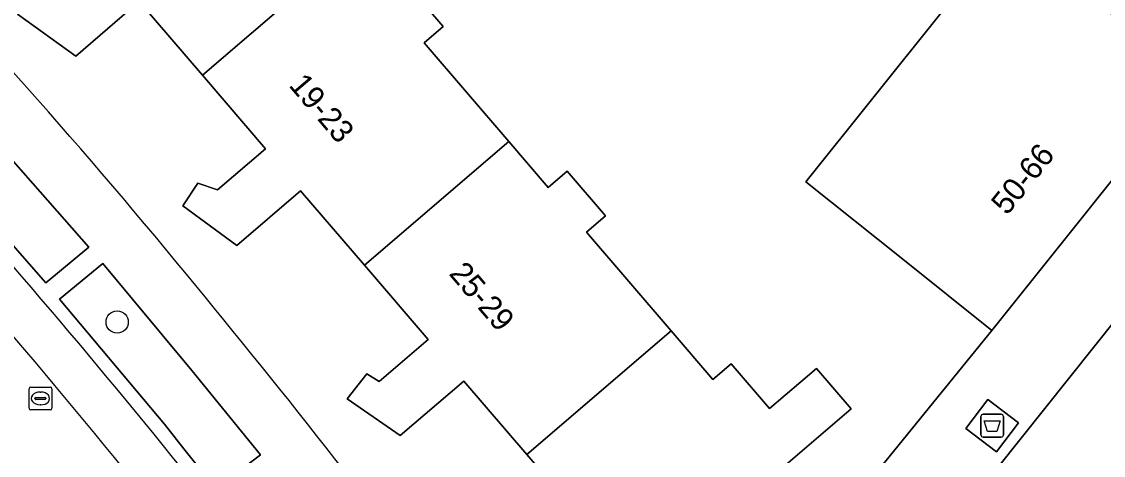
# Model space of a CAD drawing. Extents: x 159888 to 160761, y 384031 to 384750.
# Drawn here: x 160231.32 to 160278.81, y 384372.87 to 384391.93 of the extents above; entities that cross this region are included whole.
import ezdxf

# ---------------------------------------------------------------- set-up
doc = ezdxf.new("R2010")
doc.units = 0
for name, color, linetype in [('IMGEO_Afval_apart_plaats', 7, 'Continuous'), ('IMGEO_Berm_groen', 7, 'Continuous'), ('IMGEO_Boom', 7, 'Continuous'), ('IMGEO_Erf', 7, 'Continuous'), ('IMGEO_Fietspad_gesloten', 7, 'Continuous'), ('IMGEO_Groenvoorziening', 7, 'Continuous'), ('IMGEO_Pand', 7, 'Continuous'), ('IMGEO_Pand_nummerreeks', 7, 'Continuous'), ('IMGEO_Parkeervlak_open', 7, 'Continuous'), ('IMGEO_Rijbaan_lokaal_open', 7, 'Continuous'), ('IMGEO_Rioolput', 7, 'Continuous'), ('IMGEO_Voetpad_gesloten', 7, 'Continuous'), ('IMGEO_Voetpad_open', 7, 'Continuous')]:
    doc.layers.add(name, color=color, linetype=linetype)

msp = doc.modelspace()

# ---------------------------------------------------------------- linework, layer by layer
at = {"layer": 'IMGEO_Afval_apart_plaats'}
for p, q in [((160273.44, 384373.772), (160273.44, 384374.572)), ((160273.44, 384374.572), (160273.44, 384373.772)), ((160273.54, 384374.672), (160274.33, 384374.672)), ((160274.33, 384374.672), (160273.54, 384374.672)), ((160274.43, 384374.572), (160274.43, 384373.772)), ((160274.43, 384373.772), (160274.43, 384374.572)), ((160274.33, 384373.672), (160273.54, 384373.672)), ((160273.54, 384373.672), (160274.33, 384373.672))]:
    msp.add_line(p, q, dxfattribs=at)
msp.add_lwpolyline([(160273.583, 384374.386), (160274.287, 384374.386), (160274.138, 384373.916), (160273.732, 384373.916), (160273.583, 384374.386)], dxfattribs=at)
for centre, start, end in [((160273.54, 384374.572), 90, 180), ((160273.54, 384374.572), 90, 180), ((160274.33, 384374.572), 0, 90), ((160274.33, 384374.572), 360, 90), ((160273.54, 384373.772), 180, 270), ((160273.54, 384373.772), 180, 270), ((160274.33, 384373.772), 270, 0), ((160274.33, 384373.772), 270, 0)]:
    msp.add_arc(centre, 0.1, start, end, dxfattribs=at)
at = {"layer": 'IMGEO_Berm_groen'}
msp.add_arc((159956.836, 384149.758), 348.241, 34.54418, 40.04879, dxfattribs=at)
at = {"layer": 'IMGEO_Boom'}
msp.add_circle((160235.515, 384378.728), 0.489, dxfattribs=at)
at = {"layer": 'IMGEO_Erf'}
for points in [[(160242.027, 384386.34), (160239.258, 384389.573), (160236.489, 384392.807), (160233.695, 384390.414), (160231.142, 384392.248), (160231.874, 384393.353), (160232.674, 384392.788), (160234.835, 384394.639), (160232.048, 384397.893), (160229.261, 384401.148), (160226.47, 384398.758), (160223.915, 384400.407), (160224.746, 384401.572), (160225.516, 384401.057), (160227.729, 384402.952), (160224.921, 384406.231), (160222.112, 384409.511), (160219.269, 384407.076), (160216.817, 384408.667), (160215.325, 384405.834), (160223.225, 384397.993)], [(160248.153, 384393.671), (160249.832, 384391.711), (160248.995, 384390.994), (160252.709, 384386.658), (160254.444, 384384.632), (160255.28, 384385.348), (160256.959, 384383.388), (160256.122, 384382.671), (160259.836, 384378.335), (160261.666, 384376.198), (160262.477, 384376.892), (160264.162, 384374.923), (160266.223, 384376.687), (160267.744, 384374.911), (160264.872, 384372.453), (160267.058, 384369.901), (160273.92, 384378.359), (160270.015, 384381.482), (160265.753, 384384.892), (160274.58, 384395.925)], [(160251.391, 384364.439), (160254.889, 384359.573), (160259.602, 384363.534), (160260.735, 384364.486), (160257.748, 384367.974), (160254.967, 384365.592), (160252.638, 384367.22), (160253.369, 384368.345), (160254.116, 384367.849), (160256.256, 384369.681), (160253.495, 384372.905), (160250.734, 384376.129), (160247.942, 384373.738), (160245.621, 384375.35), (160246.472, 384376.455), (160247.014, 384376.12), (160249.168, 384377.959), (160246.369, 384381.228), (160243.569, 384384.497), (160240.766, 384382.096), (160238.402, 384383.829), (160239.065, 384384.832), (160239.915, 384384.532), (160242.027, 384386.34)]]:
    msp.add_lwpolyline(points, dxfattribs=at)
for centre, radius, start, end in [((160022.988, 384203.662), 279.033, 39.41659, 44.14248), ((159928.033, 384124.513), 402.647, 36.57478, 39.53815)]:
    msp.add_arc(centre, radius, start, end, dxfattribs=at)
at = {"layer": 'IMGEO_Fietspad_gesloten'}
msp.add_arc((159956.836, 384149.758), 348.241, 34.54418, 40.04879, dxfattribs=at)
at = {"layer": 'IMGEO_Groenvoorziening'}
for points in [[(160227.106, 384390.153), (160225.267, 384388.561), (160232.388, 384380.442), (160234.273, 384382.022)], [(160234.889, 384381.305), (160232.98, 384379.738), (160237.599, 384374.245), (160238.44, 384373.16), (160239.842, 384371.394), (160241.807, 384372.897), (160238.79, 384376.591)]]:
    msp.add_lwpolyline(points, close=True, dxfattribs=at)
at = {"layer": 'IMGEO_Pand'}
for points in [[(160245.577, 384394.985), (160241.863, 384399.321), (160242.7, 384400.038), (160241.021, 384401.998), (160240.185, 384401.282), (160238.416, 384403.347), (160232.048, 384397.893), (160234.835, 384394.639), (160232.674, 384392.788), (160231.874, 384393.353), (160231.142, 384392.248), (160233.695, 384390.414), (160236.489, 384392.807), (160239.258, 384389.573)], [(160274.58, 384395.925), (160265.753, 384384.892), (160270.015, 384381.482), (160273.92, 384378.359), (160282.747, 384389.392)], [(160248.995, 384390.994), (160249.832, 384391.711), (160248.153, 384393.671), (160247.317, 384392.955), (160245.577, 384394.985), (160239.258, 384389.573), (160242.027, 384386.34), (160239.915, 384384.532), (160239.065, 384384.832), (160238.402, 384383.829), (160240.766, 384382.096), (160243.569, 384384.497), (160246.369, 384381.228), (160252.709, 384386.658)], [(160256.122, 384382.671), (160256.959, 384383.388), (160255.28, 384385.348), (160254.444, 384384.632), (160252.709, 384386.658), (160246.369, 384381.228), (160249.168, 384377.959), (160247.014, 384376.12), (160246.472, 384376.455), (160245.621, 384375.35), (160247.942, 384373.738), (160250.734, 384376.129), (160253.495, 384372.905), (160259.836, 384378.335)], [(160264.872, 384372.453), (160267.744, 384374.911), (160266.223, 384376.687), (160264.162, 384374.923), (160262.477, 384376.892), (160261.666, 384376.198), (160259.836, 384378.335), (160253.495, 384372.905), (160256.256, 384369.681), (160254.116, 384367.849), (160253.369, 384368.345), (160252.638, 384367.22), (160254.967, 384365.592), (160257.748, 384367.974), (160260.735, 384364.486), (160267.058, 384369.901)]]:
    msp.add_lwpolyline(points, close=True, dxfattribs=at)
at = {"layer": 'IMGEO_Parkeervlak_open'}
for centre, radius, start, end in [((159969.953, 384156.223), 344.563, 36.14699, 43.0255), ((159959.248, 384147.319), 356.495, 35.83006, 42.84924)]:
    msp.add_arc(centre, radius, start, end, dxfattribs=at)
at = {"layer": 'IMGEO_Rijbaan_lokaal_open'}
msp.add_lwpolyline([(160279.413, 384378.913), (160266.78, 384363.051), (160262.944, 384358.346), (160260.04, 384354.657), (160258.945, 384353.29), (160259.2, 384353.077), (160263.16, 384349.885), (160264.977, 384352.272), (160267.652, 384355.612), (160279.613, 384370.408)], dxfattribs=at)
msp.add_arc((159959.248, 384147.319), 356.495, 35.83006, 42.84924, dxfattribs=at)
at = {"layer": 'IMGEO_Rioolput'}
for p, q in [((160231.647, 384374.943), (160231.647, 384375.795)), ((160231.722, 384375.869), (160232.574, 384375.869)), ((160232.648, 384375.795), (160232.648, 384374.943)), ((160231.906, 384375.363), (160231.906, 384375.375)), ((160232.344, 384375.326), (160231.946, 384375.326)), ((160231.949, 384375.412), (160232.347, 384375.412)), ((160232.135, 384375.649), (160232.16, 384375.649)), ((160232.39, 384375.375), (160232.39, 384375.363)), ((160232.574, 384374.869), (160231.722, 384374.869)), ((160232.158, 384375.089), (160232.133, 384375.089))]:
    msp.add_line(p, q, dxfattribs=at)
for points in [[(160231.647, 384374.943), (160231.647, 384375.795)], [(160231.722, 384375.869), (160232.574, 384375.869)], [(160232.648, 384375.795), (160232.648, 384374.943)], [(160232.574, 384374.869), (160231.722, 384374.869)]]:
    msp.add_lwpolyline(points, dxfattribs=at)
for centre, radius, start, end in [((160231.724, 384375.793), 0.0765, 91.552, 178.448), ((160231.724, 384375.793), 0.0765, 91.552, 178.448), ((160232.572, 384375.793), 0.0765, 1.552, 88.448), ((160232.572, 384375.793), 0.0765, 1.552, 88.448), ((160231.946, 384375.372), 0.0403, 85.8775, 175.7526), ((160231.943, 384375.362), 0.0366, 178.938, 274.7102), ((160232.347, 384375.369), 0.043, 264.8664, 352.4533), ((160232.351, 384375.374), 0.0386, 1.7309, 96.639), ((160231.724, 384374.945), 0.0765, 181.552, 268.448), ((160231.724, 384374.945), 0.0765, 181.552, 268.448), ((160232.572, 384374.945), 0.0765, 271.552, 358.448), ((160232.572, 384374.945), 0.0765, 271.552, 358.448)]:
    msp.add_arc(centre, radius, start, end, dxfattribs=at)
for centre, major_axis, ratio, start_param, end_param in [((160232.134, 384375.369), (-0.387, 0.002), 0.722429, 4.712389, 7.853982), ((160232.159, 384375.369), (-0.39, 0.002), 0.717154, 1.570796, 4.712389)]:
    msp.add_ellipse(centre, major_axis=major_axis, ratio=ratio, start_param=start_param, end_param=end_param, dxfattribs=at)
at = {"layer": 'IMGEO_Voetpad_gesloten'}
msp.add_lwpolyline([(160275.095, 384374.301), (160273.744, 384375.324), (160272.775, 384374.044), (160274.126, 384373.021)], close=True, dxfattribs=at)
at = {"layer": 'IMGEO_Voetpad_open'}
msp.add_lwpolyline([(160340.54, 384395.48), (160338.468, 384397.105), (160335.895, 384399.076), (160307.955, 384420.899), (160300.402, 384411.459), (160291.575, 384400.426), (160282.747, 384389.392), (160273.92, 384378.359), (160267.058, 384369.901), (160260.735, 384364.486), (160259.602, 384363.534), (160261.313, 384361.982), (160256.658, 384356.833), (160258.945, 384353.29), (160260.04, 384354.657), (160262.944, 384358.346), (160266.78, 384363.051), (160279.413, 384378.913)], dxfattribs=at)
for points in [[(160232.388, 384380.442), (160225.267, 384388.561), (160227.106, 384390.153), (160234.273, 384382.022)], [(160234.889, 384381.305), (160238.79, 384376.591), (160241.807, 384372.897), (160239.842, 384371.394), (160238.44, 384373.16), (160237.599, 384374.245), (160232.98, 384379.738)], [(160273.744, 384375.324), (160275.095, 384374.301), (160274.126, 384373.021), (160272.775, 384374.044)]]:
    msp.add_lwpolyline(points, close=True, dxfattribs=at)
for centre, radius, start, end in [((160022.988, 384203.662), 279.033, 39.41659, 44.14248), ((159969.953, 384156.223), 344.563, 36.14699, 43.0255), ((159928.033, 384124.513), 402.647, 36.57478, 39.53815)]:
    msp.add_arc(centre, radius, start, end, dxfattribs=at)

# ---------------------------------------------------------------- texts
at = {"layer": 'IMGEO_Pand_nummerreeks'}
for s, rotation, p in [('19-23', 310.4506, (160243.016, 384389.114)), ('50-66', 51.3124, (160274.587, 384383.378)), ('25-29', 310.5996, (160250.048, 384380.833))]:
    msp.add_text(s, height=1, rotation=rotation, dxfattribs=at).set_placement(p)

doc.saveas('drawing.dxf')
